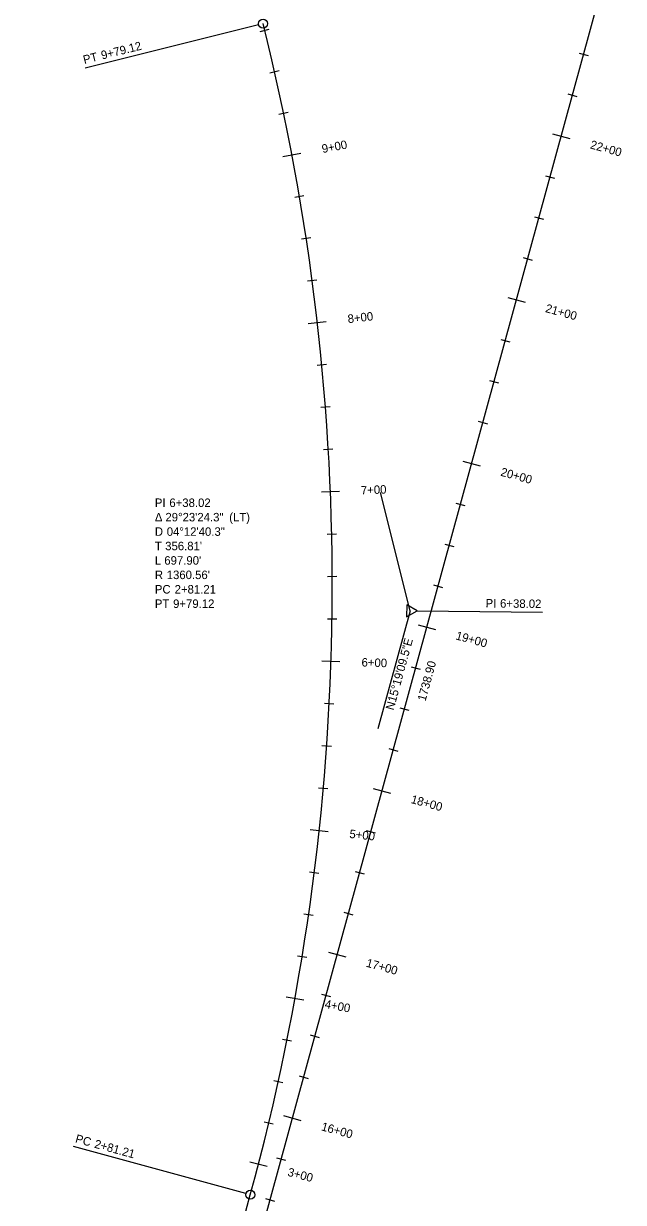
# Model space of a CAD drawing. Extents: x 2300830 to 2307917, y 756066 to 766359.
# Drawn here: x 2302468 to 2302821, y 760306 to 761001 of the extents above; entities that cross this region are included whole.
import ezdxf

# ---------------------------------------------------------------- set-up
doc = ezdxf.new("R2010")
doc.units = 0
for name, color, linetype in [('Default', 7, 'Continuous'), ('Draft_Bearing Label', 7, 'Continuous'), ('Draft_Curve Data Label', 7, 'Continuous'), ('Draft_Station Cardinal Lines', 7, 'Continuous'), ('Draft_Station Cardinal Points', 7, 'Continuous'), ('Draft_Station Labels Major', 7, 'Continuous'), ('Draft_Station Ticks Major', 7, 'Continuous'), ('Draft_Station Ticks Minor', 7, 'Continuous'), ('Geom_Baseline', 7, 'Continuous')]:
    doc.layers.add(name, color=color, linetype=linetype)

msp = doc.modelspace()

# ---------------------------------------------------------------- linework, layer by layer
at = {"layer": 'Default'}
for p, q in [((2302467.58, 759777.24), (2302927, 761454.36)), ((2302526.92, 760039.15), (2302601.22, 760310.37))]:
    msp.add_line(p, q, dxfattribs=at)
msp.add_arc((2301289, 760669.82), 1360.56, 344.6807, 14.07079, dxfattribs=at)
at = {"layer": 'Draft_Station Cardinal Lines'}
for p, q in [((2302606.15, 760999.95), (2302503.98, 760974.35)), ((2302695.48, 760654.5), (2302677.98, 760724.34)), ((2302695.48, 760654.5), (2302676.46, 760585.06)), ((2302699.68, 760654.45), (2302773.48, 760653.65)), ((2302598.64, 760311.07), (2302497.05, 760338.9))]:
    msp.add_line(p, q, dxfattribs=at)
msp.add_lwpolyline([(2302699.64, 760654.45), (2302693.45, 760658.12), (2302693.37, 760650.92)], close=True, dxfattribs=at)
at = {"layer": 'Draft_Station Cardinal Points'}
for p, q in [((2302503.98, 760974.35), (2302503.98, 760974.35)), ((2302695.48, 760654.5), (2302695.48, 760654.5)), ((2302773.48, 760653.65), (2302773.48, 760653.65)), ((2302497.05, 760338.9), (2302497.05, 760338.9)), ((2302601.22, 760310.37), (2302601.22, 760310.37))]:
    msp.add_line(p, q, dxfattribs=at)
for centre in [(2302608.74, 761000.6), (2302601.22, 760310.37)]:
    msp.add_circle(centre, 2.67, dxfattribs=at)
at = {"layer": 'Draft_Station Ticks Major'}
for p, q in [((2302779.38, 760935.69), (2302789.62, 760932.88)), ((2302620.48, 760922.35), (2302630.92, 760924.33)), ((2302752.96, 760839.24), (2302763.2, 760836.43)), ((2302635.43, 760823.89), (2302645.98, 760825.1)), ((2302726.54, 760742.79), (2302736.78, 760739.99)), ((2302643.11, 760724.61), (2302653.72, 760725.04)), ((2302700.12, 760646.35), (2302710.36, 760643.54)), ((2302643.48, 760625.02), (2302654.09, 760624.67)), ((2302673.7, 760549.9), (2302683.94, 760547.09)), ((2302636.53, 760525.68), (2302647.09, 760524.55)), ((2302647.28, 760453.45), (2302657.52, 760450.65)), ((2302622.31, 760427.12), (2302632.76, 760425.21)), ((2302620.86, 760357.01), (2302631.1, 760354.2)), ((2302600.89, 760329.86), (2302611.17, 760327.2))]:
    msp.add_line(p, q, dxfattribs=at)
at = {"layer": 'Draft_Station Ticks Minor'}
for p, q in [((2302607.05, 760995.95), (2302612.41, 760997.27)), ((2302795.08, 760983.23), (2302800.4, 760981.77)), ((2302612.82, 760971.67), (2302618.2, 760972.9)), ((2302788.47, 760959.12), (2302793.8, 760957.66)), ((2302618.14, 760947.3), (2302623.55, 760948.43)), ((2302775.26, 760910.89), (2302780.59, 760909.43)), ((2302627.44, 760898.28), (2302632.88, 760899.21)), ((2302768.66, 760886.78), (2302773.98, 760885.32)), ((2302631.41, 760873.65), (2302636.87, 760874.48)), ((2302762.05, 760862.67), (2302767.38, 760861.21)), ((2302634.93, 760848.95), (2302640.4, 760849.68)), ((2302748.84, 760814.45), (2302754.17, 760812.99)), ((2302640.6, 760799.38), (2302646.1, 760799.9)), ((2302742.24, 760790.33), (2302747.56, 760788.88)), ((2302642.76, 760774.52), (2302648.26, 760774.95)), ((2302735.63, 760766.22), (2302740.96, 760764.76)), ((2302644.45, 760749.63), (2302649.96, 760749.95)), ((2302722.42, 760718), (2302727.75, 760716.54)), ((2302646.47, 760699.77), (2302651.99, 760699.9)), ((2302715.82, 760693.89), (2302721.14, 760692.43)), ((2302646.79, 760674.83), (2302652.31, 760674.85)), ((2302709.21, 760669.78), (2302714.54, 760668.32)), ((2302646.65, 760649.88), (2302652.17, 760649.8)), ((2302696, 760621.55), (2302701.33, 760620.09)), ((2302645, 760600.01), (2302650.52, 760599.73)), ((2302689.4, 760597.44), (2302694.72, 760595.98)), ((2302643.49, 760575.11), (2302649, 760574.72)), ((2302682.8, 760573.33), (2302688.12, 760571.87)), ((2302641.52, 760550.24), (2302647.02, 760549.75)), ((2302669.59, 760525.11), (2302674.91, 760523.65)), ((2302636.22, 760500.62), (2302641.69, 760499.93)), ((2302662.98, 760500.99), (2302668.3, 760499.54)), ((2302632.88, 760475.9), (2302638.34, 760475.11)), ((2302656.38, 760476.88), (2302661.7, 760475.42)), ((2302629.09, 760451.24), (2302634.54, 760450.35)), ((2302643.17, 760428.66), (2302648.49, 760427.2)), ((2302636.56, 760404.55), (2302641.88, 760403.09)), ((2302620.15, 760402.15), (2302625.56, 760401.06)), ((2302615.01, 760377.74), (2302620.4, 760376.55)), ((2302629.96, 760380.44), (2302635.28, 760378.98)), ((2302609.42, 760353.42), (2302614.79, 760352.14)), ((2302616.75, 760332.21), (2302622.07, 760330.75)), ((2302610.14, 760308.1), (2302615.46, 760306.64))]:
    msp.add_line(p, q, dxfattribs=at)
at = {"layer": 'Geom_Baseline'}
for p, q in [((2302467.58, 759777.24), (2302927, 761454.36)), ((2302526.92, 760039.15), (2302601.22, 760310.37))]:
    msp.add_line(p, q, dxfattribs=at)
msp.add_arc((2301289, 760669.82), 1360.56, 344.6807, 14.07079, dxfattribs=at)

# ---------------------------------------------------------------- texts
at = {"layer": 'Draft_Bearing Label'}
for s, p in [('N15°19\'09.5"E', (2302685.67, 760595.62)), ('1738.90', (2302704.49, 760600.92))]:
    msp.add_text(s, height=5, rotation=74.6807, dxfattribs=at).set_placement(p)
at = {"layer": 'Draft_Curve Data Label'}
for s, p in [('PI ', (2302544.98, 760715.72)), ('6+38.02', (2302553.52, 760715.72)), ('Δ ', (2302544.98, 760707.22)), ('29°23\'24.3"', (2302551.2, 760707.22)), (' (LT)', (2302586.93, 760707.22)), ('D ', (2302544.98, 760698.72)), ('04°12\'40.3"', (2302551.97, 760698.72)), ('T ', (2302544.98, 760690.22)), ("356.81'", (2302551.06, 760690.22)), ('L ', (2302544.98, 760681.72)), ("697.90'", (2302550.54, 760681.72)), ('R ', (2302544.98, 760673.22)), ("1360.56'", (2302551.97, 760673.22)), ('PC ', (2302544.98, 760664.72)), ('2+81.21', (2302556.63, 760664.72)), ('PT ', (2302544.98, 760656.22)), ('9+79.12', (2302555.72, 760656.22))]:
    msp.add_text(s, height=5, dxfattribs=at).set_placement(p)
at = {"layer": 'Draft_Station Cardinal Points'}
for s, rotation, p in [('9+79.12', 14.07079, (2302513.92, 760979.4)), ('PT', 14.07079, (2302503.37, 760976.76)), ('PI ', 359.37575, (2302739.9, 760656.5)), ('6+38.02', 359.37575, (2302748.44, 760656.41)), ('PC', 344.6807, (2302497.71, 760341.3)), ('2+81.21', 344.6807, (2302508.94, 760338.22))]:
    msp.add_text(s, height=5, rotation=rotation, dxfattribs=at).set_placement(p)
at = {"layer": 'Draft_Station Labels Major'}
for s, rotation, p in [('9+00', 10.73909, (2302643.88, 760924.24)), ('22+00', 344.6807, (2302801.23, 760927.11)), ('21+00', 344.6807, (2302774.81, 760830.66)), ('8+00', 6.52789, (2302658.91, 760824.06)), ('20+00', 344.6807, (2302748.39, 760734.22)), ('7+00', 2.31668, (2302666.53, 760723.05)), ('19+00', 344.6807, (2302721.97, 760637.77)), ('6+00', 358.10548, (2302666.72, 760621.75)), ('18+00', 344.6807, (2302695.55, 760541.32)), ('5+00', 353.89427, (2302659.47, 760520.71)), ('17+00', 344.6807, (2302669.13, 760444.87)), ('4+00', 349.68307, (2302644.82, 760420.48)), ('16+00', 344.6807, (2302642.71, 760348.43)), ('3+00', 345.47186, (2302622.85, 760321.59))]:
    msp.add_text(s, height=5, rotation=rotation, dxfattribs=at).set_placement(p)

doc.saveas('drawing.dxf')
